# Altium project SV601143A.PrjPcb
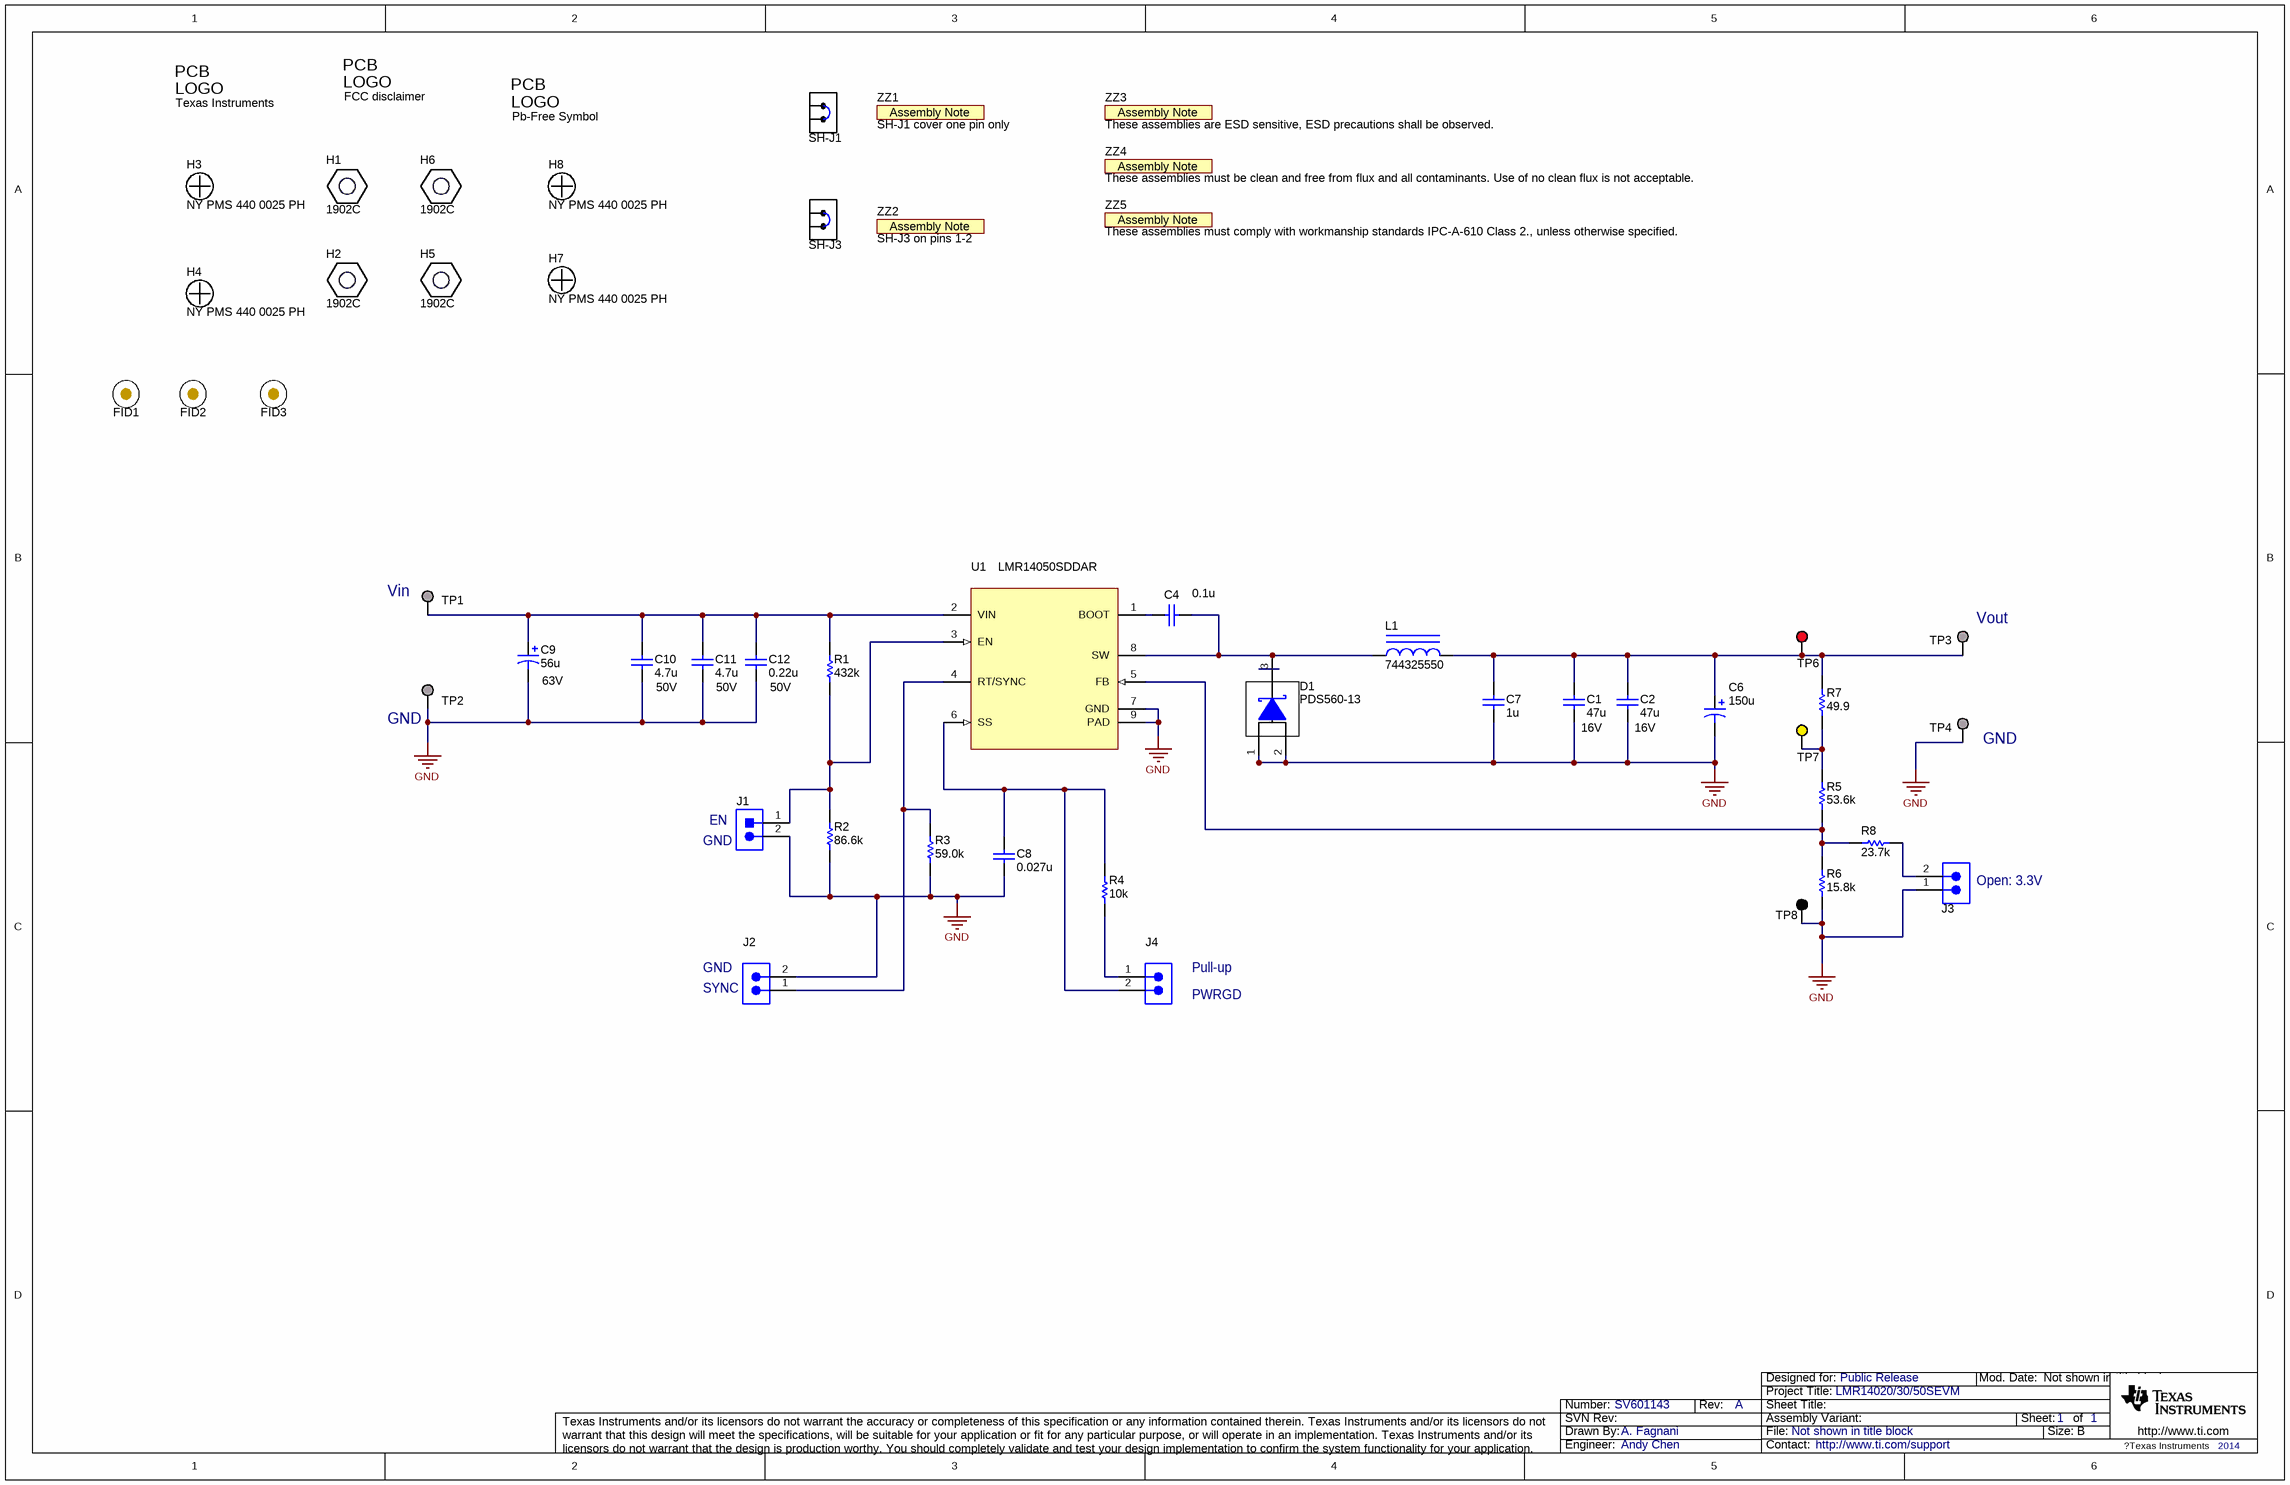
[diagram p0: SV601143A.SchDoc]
CopyrightYear: 2014; PCB_Layout: Andy Chen; PCB_Rev: A; PRJ_Customer: Public Release; PRJ_Engineer: Andy Chen; PRJ_Number: SV601143; PRJ_Title: LMR14020/30/50SEVM; SCH_Rev: A; TechSupport: http://www.ti.com/support
1 sheet, 53 parts. Net scope: global (net labels, ports and power ports of the same name join across sheets).
Board file: SV601143A.PcbDoc

## Sheet SV601143A.SchDoc
size 431 x 279 mm; Date: Not shown in title block; ApprovedBy: Not shown in title block; CheckedBy: Not shown in title block; Author: Not shown in title block; CompanyName: Not shown in title block; DrawnBy: A. Fagnani; Engineer: Not shown in title block; Organization: Not shown in title block; Address1: Not shown in title block; Address2: Not shown in title block; Address3: Not shown in title block; Address4: Not shown in title block; DocumentNumber: 1; Revision: Use project parameter SCH_Rev; SheetNumber: 1; SheetTotal: 1; PageSetup: Record=PageOptions|CenterHorizontal=True|CenterVertical=True|PrintScale=1.00|XCorrection=1.00|YCorrection=1.00|PrintKind=0|BorderSize=5000000|LeftOffset=0|BottomOffset=0|Orientation=2|PaperLength=1000|PaperWidth=1000|Scale=100|PaperSource=15|PrintQuality=600|MediaType=1|DitherType=10|PaperKind=Letter|PrintScaleMode=1

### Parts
C1  ValueDisplayed: 47u  VDC_V: 16V  [1210]  (hidden comment: GRM32ER61C476ME15L)
C2  ValueDisplayed: 47u  VDC_V: 16V  [1210]  (hidden comment: GRM32ER61C476ME15L)
C4  ValueDisplayed: 0.1u  [0603]  (hidden comment: GRM188R71C104KA01D)
C6  ValueDisplayed: 150u  [7343-28]  (hidden comment: 16TQC150MYF)
C7  ValueDisplayed: 1u  [0805_HV]  (hidden comment: GRM21BR71E105KA99L)
C8  ValueDisplayed: 0.027u  [0603]  (hidden comment: C0603C273K1RACTU)
C9  ValueDisplayed: 56u  Value2: 63V  [SM_RADIAL_10BMM]  (hidden comment: EEHZA1J560P)
C10  ValueDisplayed: 4.7u  VDC_V: 50V  [1210]  (hidden comment: GRM32ER71H475KA88L)
C11  ValueDisplayed: 4.7u  VDC_V: 50V  [1210]  (hidden comment: GRM32ER71H475KA88L)
C12  ValueDisplayed: 0.22u  VDC_V: 50V  [0805_HV]  (hidden comment: GRM21BR71H224KA01L)
D1  PDS560-13  [PowerDI5]
FID1  Fiducial  [Fiducial10-20]  (value not drawn)
FID2  Fiducial  [Fiducial10-20]  (value not drawn)
FID3  Fiducial  [Fiducial10-20]  (value not drawn)
H1  1902C  [Keystone_1902C]
H2  1902C  [Keystone_1902C]
H3  NY PMS 440 0025 PH  [NY PMS 440 0025 PH]
H4  NY PMS 440 0025 PH  [NY PMS 440 0025 PH]
H5  1902C  [Keystone_1902C]
H6  1902C  [Keystone_1902C]
H7  NY PMS 440 0025 PH  [NY PMS 440 0025 PH]
H8  NY PMS 440 0025 PH  [NY PMS 440 0025 PH]
J1  TSW-102-07-G-S  [TSW-102-07-G-S]  (value not drawn)
J2  TSW-102-07-G-S  [TSW-102-07-G-S]  (value not drawn)
J3  TSW-102-07-G-S  [TSW-102-07-G-S]  (value not drawn)
J4  TSW-102-07-G-S  [TSW-102-07-G-S]  (value not drawn)
L1  744325550  [WE-HC6]
Logo1  Texas Instruments  [TI_Stacked_Overlay_Small]  (no BOM)
Logo2  FCC disclaimer  [FCC_disclaimer_stacked]  (no BOM)
Logo3  Pb-Free Symbol  [Pb-Free_Overlay_Medium]  (no BOM)
R1  ValueDisplayed: 432k  [0603]  (hidden comment: CRCW0603432KFKEA)
R2  ValueDisplayed: 86.6k  [0603]  (hidden comment: CRCW060386K6FKEA)
R3  ValueDisplayed: 59.0k  [0603]  (hidden comment: CRCW060359K0FKEA)
R4  ValueDisplayed: 10k  [0603]  (hidden comment: CRCW060310K0JNEA)
R5  value 53.6k  [0603]  (hidden comment: CRCW060353K6FKEA)
R6  ValueDisplayed: 15.8k  [0603]  (hidden comment: CRCW060315K8FKEA)
R7  value 49.9  [0603]  (hidden comment: CRCW060349R9FKEA)
R8  ValueDisplayed: 23.7k  [0603]  (hidden comment: CRCW060323K7FKEA)
SH-J1  SPC02SYAN  [SPC02SYAN]  (value not drawn)
SH-J3  SPC02SYAN  [SPC02SYAN]  (value not drawn)
TP1  Suggest using a net name here  [Keystone1502-2]  (value not drawn)
TP2  Suggest using a net name here  [Keystone1502-2]  (value not drawn)
TP3  Suggest using a net name here  [Keystone1502-2]  (value not drawn)
TP4  Suggest using a net name here  [Keystone1502-2]  (value not drawn)
TP6  5010  [Keystone5010]  (value not drawn)
TP7  5014  [Keystone5014]  (value not drawn)
TP8  5011  [Keystone5011]  (value not drawn)
U1  LMR14050SDDAR  [DDA0008E_N]
ZZ1  SH-J1 cover one pin only  [AssemblyNote]  (no BOM)
ZZ2  SH-J3 on pins 1-2  [AssemblyNote]  (no BOM)
ZZ3  These assemblies are ESD sensitive, ESD precautions shall be observed.  [AssemblyNote]  (no BOM)
ZZ4  These assemblies must be clean and free from flux and all contaminants. Use of no clean flux is not acceptable.  [AssemblyNote]  (no BOM)
ZZ5  These assemblies must comply with workmanship standards IPC-A-610 Class 2., unless otherwise specified.  [AssemblyNote]  (no BOM)

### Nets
GND: C1.2 C2.2 C6.2(-) C7.2 C8.2 C9.2(-) C10.2 C11.2 C12.2 D1.1(A) D1.2(A) J1.2 J2.2 J3.1 R2.1 R3.1 R6.1 TP2.1 TP4.1 TP8.1 U1.7(GND) U1.9(PAD)
NetC1_1: C1.1 C2.1 C6.1(+) C7.1 L1.2 R7.2 TP3.1 TP6.1
NetC4_1: C4.1 D1.3(K) L1.1 U1.8(SW)
NetC4_2: C4.2 U1.1(BOOT)
NetC8_1: C8.1 J4.2 R4.2 U1.6(SS)
NetC9_1: C9.1(+) C10.1 C11.1 C12.1 R1.2 TP1.1 U1.2(VIN)
NetJ1_1: J1.1 R1.1 R2.2 U1.3(EN)
NetJ2_1: J2.1 R3.2 U1.4(RT/SYNC)
NetJ3_2: J3.2 R8.1
NetJ4_1: J4.1 R4.1
NetR5_1: R5.1 R6.2 R8.2 U1.5(FB)
NetR5_2: R5.2 R7.1 TP7.1

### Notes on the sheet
- (near TP1) Vin
- (near TP3) Vout
- (near TP2) GND
- (near TP4) GND
- (near J1) EN
- (near J1) GND
- (near J3) Open: 3.3V
- (near J2) GND
- (near J4) Pull-up
- (near J2) SYNC
- (near J4) PWRGD

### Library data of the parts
C1 C2 = GRM32ER61C476ME15L: CAP, CERM, 47uF, 16V, +/-20%, X5R, 1210; Manufacturer: MuRata; Polarized: N; CompType: Capacitor; U/M: EA; Cap_F: 0.000047; Tolerance_%: 20; ESR_Ohm: 0.002; Value1: 0.002 ohm; TaMin_C: -55; TaMax_C: 85
C4 = GRM188R71C104KA01D: CAP, CERM, 0.1 µF, 16 V, +/- 10%, X7R, 0603; Manufacturer: MuRata; Polarized: N; CompType: Capacitor; Value: 0.1uF; U/M: EA; Cap_F: 0.0000001; Tolerance_%: 10; Value1: Unknown; VDC_V: 16; Value2: 16V; TaMin_C: -55; TaMax_C: 125
C6 = 16TQC150MYF: CAP, TA, 150 µF, 16 V, +/- 20%, 0.05 ohm, SMD; Manufacturer: Panasonic; Value: 150uF; Polarized: Y; CompType: Capacitor; U/M: EA; Cap_F: 0.00015; Tolerance_%: 20; VDC_V: 16; Value2: 16V; ESR_ohm: 0.05; IRMS_A: 1.8; TaMin_C: -55; TaMax_C: 105; Cap_Case: 7.3x2.8x4.3
C7 = GRM21BR71E105KA99L: CAP, CERM, 1 µF, 25 V, +/- 10%, X7R, 0805; Manufacturer: MuRata; Polarized: N; CompType: Capacitor; Value: 1uF; U/M: EA; Cap_F: 0.000001; Tolerance_%: 10; Value1: Unknown; VDC_V: 25; Value2: 25V; TaMin_C: -55; TaMax_C: 125; Cap_Case: 0805
C8 = C0603C273K1RACTU: CAP, CERM, 0.027 µF, 100 V, +/- 10%, X7R, 0603; Manufacturer: Kemet; Polarized: N; CompType: Capacitor; Value: 0.027uF; U/M: EA; Cap_F: 0.000000027; Tolerance_%: 10; Value1: Unknown; VDC_V: 100; Value2: 100V; TaMin_C: -55; TaMax_C: 125
C9 = EEHZA1J560P: CAP, AL, 56 µF, 63 V, +/- 20%, 30 ohm, SMD; Manufacturer: Panasonic; Polarized: Y; CompType: Capacitor; Value: 56uF; U/M: EA; Cap_F: 0.000056; Tolerance_%: 20; Value1: 30 ohm; VDC_V: 63; ESR_ohm: 30; IRMS_A: 1.8; TaMin_C: -55; TaMax_C: 105
C10 C11 = GRM32ER71H475KA88L: CAP, CERM, 4.7uF, 50V, +/-10%, X7R, 1210; Manufacturer: MuRata; Polarized: N; CompType: Capacitor; U/M: EA; Cap_F: 0.0000047; Tolerance_%: 10; ESR_Ohm: 0.002; Value1: 0.002 ohm; TaMin_C: -55; TaMax_C: 125
C12 = GRM21BR71H224KA01L: CAP, CERM, 0.22 µF, 50 V, +/- 10%, X7R, 0805; Manufacturer: MuRata; Polarized: N; CompType: Capacitor; Value: 0.22uF; U/M: EA; Cap_F: 0.00000022; Tolerance_%: 10; Value1: Unknown; TaMin_C: -55; TaMax_C: 125; Cap_Case: 0805
D1 = PDS560-13: Diode, Schottky, 60 V, 5 A, PowerDI5; Manufacturer: Diodes Inc.; Value: 60V; U/M: EA; Vf_V: 0.67; Value1: 5A; Value2: 0.67V; Io_A: 5; Vr_V: 60; TJmax_C: 150
FID1-FID3 = Fiducial: Fiducial mark.  There is nothing to buy or mount.; SymbolCreator: codlsc
H1 H2 H5 H6 = 1902C: Standoff, Hex, 0.5"L #4-40 Nylon; Manufacturer: Keystone; CompType: Hardware
H3 H4 H7 H8 = NY PMS 440 0025 PH: Machine Screw, Round, #4-40 x 1/4, Nylon, Philips panhead; Manufacturer: B&F Fastener Supply; CompType: Hardware; SymbolCreator: codlsc; U/M: EA
J1 = TSW-102-07-G-S: Header, 100mil, 2x1, Gold, TH; Manufacturer: Samtec; U/M: EA; SymbolCreator: a0412235
J2-J4 = TSW-102-07-G-S: Header, TH, 100mil, 2x1, Gold plated, 230 mil above insulator; Manufacturer: Samtec, Inc.; U/M: EA
L1 = 744325550: Inductor, Shielded Drum Core, Superflux, 5.5 µH, 10 A, 0.0112 ohm, SMD; Manufacturer: Wurth Elektronik eiSos; Value: 5.5uH; ValueDisplayed: 5.5µH; Ind_H: 5.5E-6; Imax_A: 10; Irms: 10A @ 50C rise; Isat: 12A @ 30% inductance drop; DCR_ohm: 0.0112; Value2: 10A
Logo1 = TI_Logo: Texas Instrument Corporate Signature; SymbolCreator: codlsc
Logo2 = FCC_disclaimer: SymbolCreator: codlsc
Logo3 = Pb-Free: SymbolCreator: a0412235
R1 = CRCW0603432KFKEA: RES, 432 k, 1%, 0.1 W, 0603; Manufacturer: Vishay-Dale; CompType: Resistor; Value: 432k; Res_ohm: 432000; Tolerance_%: 1; Power_W: 0.1; Value2: 0.1W; VDC_V: 75; TempCo: 100 ppm/C; EIA_Code: E96; U/M: EA
R2 = CRCW060386K6FKEA: RES, 86.6 k, 1%, 0.1 W, 0603; Manufacturer: Vishay-Dale; CompType: Resistor; Value: 86.6k; Res_ohm: 86600; Value_Code: 86k6; Tolerance_%: 1; Power_W: 0.1; Value2: 0.1W; VDC_V: 75; TempCo: 100 ppm/C; EIA_Code: E96; U/M: EA
R3 = CRCW060359K0FKEA: RES, 59.0 k, 1%, 0.1 W, 0603; Manufacturer: Vishay-Dale; CompType: Resistor; Value: 59.0k; Res_ohm: 59000; Value_Code: 59k0; Tolerance_%: 1; Power_W: 0.1; Value2: 0.1W; VDC_V: 75; TempCo: 100 ppm/C; EIA_Code: E96; U/M: EA
R4 = CRCW060310K0JNEA: RES, 10 k, 5%, 0.1 W, 0603; Manufacturer: Vishay-Dale; CompType: Resistor; Value: 10k; Res_ohm: 10000; Value_Code: 10k0; Tolerance_%: 5; Power_W: 0.1; Value2: 0.1W; VDC_V: 75; TempCo: 200 ppm/C; EIA_Code: E24; U/M: EA
R5 = CRCW060353K6FKEA: RES, 53.6k ohm, 1%, 0.1W, 0603; Manufacturer: Vishay-Dale; Alternate Manufacturer: Any; Alternate PartNumber: Equivalent; CompType: Resistor; Res_ohm: 53600; Value_Code: 53k6; Tolerance_%: 1; Power_W: 0.1; VDC_V: 75; TempCo: 100 ppm/C; EIA_Code: E96; U/M: EA
R6 = CRCW060315K8FKEA: RES, 15.8 k, 1%, 0.1 W, 0603; Manufacturer: Vishay-Dale; CompType: Resistor; Value: 15.8k; Res_ohm: 15800; Value_Code: 15k8; Tolerance_%: 1; Power_W: 0.1; Value2: 0.1W; VDC_V: 75; TempCo: 100 ppm/C; EIA_Code: E96; U/M: EA
R7 = CRCW060349R9FKEA: RES, 49.9 ohm, 1%, 0.1W, 0603; Manufacturer: Vishay-Dale; Alternate Manufacturer: Any; Alternate PartNumber: Equivalent; CompType: Resistor; Value_Code: 49R9; Tolerance_%: 1; Power_W: 0.1; VDC_V: 75; TempCo: 100 ppm/C; EIA_Code: E96; U/M: EA
R8 = CRCW060323K7FKEA: RES, 23.7 k, 1%, 0.1 W, 0603; Manufacturer: Vishay-Dale; CompType: Resistor; Value: 23.7k; Res_ohm: 23700; Value_Code: 23k7; Tolerance_%: 1; Power_W: 0.1; Value2: 0.1W; VDC_V: 75; TempCo: 100 ppm/C; EIA_Code: E96; U/M: EA
SH-J1 SH-J3 = SPC02SYAN: Shunt, 100mil, Flash Gold, Black; Manufacturer: Sullins Connector Solutions; Value: 1x2; Note: You can "mate" this to a header by matching the designator.  i.e. use SH-J3 for header J3
TP1-TP4 = 1502-2: Terminal, Turret, TH, Double; Manufacturer: Keystone; CompType: Turret Terminal; U/M: EA
TP6 = 5010: Test Point, TH, Multipurpose, Red; Manufacturer: Keystone; CompType: Test Point Loop; U/M: EA
TP7 = 5014: Test Point, Multipurpose, Yellow, TH; Manufacturer: Keystone; CompType: Test Point Loop; U/M: EA
TP8 = 5011: Test Point, TH, Multipurpose, Black; Manufacturer: Keystone; CompType: Test Point Loop; U/M: EA
U1 = LMR14050SDDAR: LMR14050SDDAR, DDA0008E; Alternate PartNumber: LMR14050SDDAT; Manufacturer: Texas Instruments; SymbolCreator: Altium; CompType: IC; U/M: EA
ZZ1-ZZ5 = AssemblyNote: SymbolCreator: codlsc

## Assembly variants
001: not fitted C2 C6 C9 FID1 FID2 FID3 H1 H2 H3 H4 H5 H6 H7 H8 J4 R4
002: not fitted C6 C9 FID1 FID2 FID3 H1 H2 H3 H4 H5 H6 H7 H8 J4 R4
003: not fitted C6 FID1 FID2 FID3 H1 H2 H3 H4 H5 H6 H7 H8 J4 R4; alternate parts C9 -> =PartNumber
